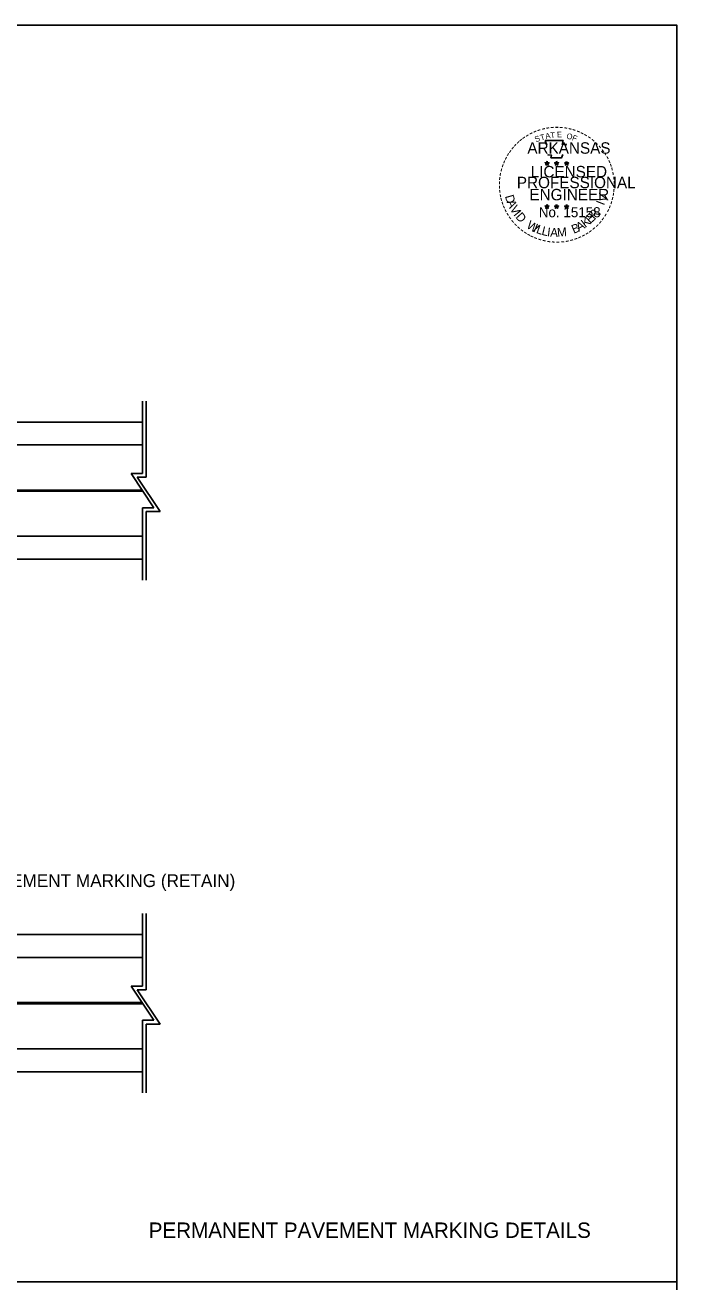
# Model space of a CAD drawing. Extents: x 1372926 to 1373096, y 381240 to 381790.
# Drawn here: x 1373038.9 to 1373096, y 381680.2 to 381790.2 of the extents above; entities that cross this region are included whole.
import ezdxf

# ---------------------------------------------------------------- set-up
doc = ezdxf.new("R2010")
doc.units = 0
for name, color, linetype in [('Default', 7, 'Continuous'), ('DSN_DRFT_Junk-No-Plot', 7, 'Continuous'), ('R_Border Notes', 7, 'Continuous'), ('R_Draft', 7, 'Continuous'), ('SHET_Border-Text', 7, 'Continuous')]:
    doc.layers.add(name, color=color, linetype=linetype)

msp = doc.modelspace()

# ---------------------------------------------------------------- linework, layer by layer
at = {"layer": 'Default'}
for p, q in [((1373049.17, 381757.27), (1373049.17, 381750.93)), ((1373049.5, 381757.27), (1373049.5, 381750.6)), ((1373049.17, 381750.93), (1373048.17, 381750.93)), ((1373050.17, 381747.93), (1373048.17, 381750.93)), ((1373050.72, 381747.6), (1373048.72, 381750.6)), ((1373049.5, 381750.6), (1373048.72, 381750.6)), ((1373049.17, 381741.59), (1373049.17, 381747.93)), ((1373049.17, 381747.93), (1373050.17, 381747.93)), ((1373049.5, 381741.59), (1373049.5, 381747.6)), ((1373049.5, 381747.6), (1373050.72, 381747.6)), ((1373049.17, 381712.41), (1373049.17, 381706.07)), ((1373049.5, 381712.41), (1373049.5, 381705.74)), ((1373049.17, 381706.07), (1373048.17, 381706.07)), ((1373050.17, 381703.07), (1373048.17, 381706.07)), ((1373050.72, 381702.74), (1373048.72, 381705.74)), ((1373049.5, 381705.74), (1373048.72, 381705.74)), ((1373049.17, 381696.73), (1373049.17, 381703.07)), ((1373049.17, 381703.07), (1373050.17, 381703.07)), ((1373049.5, 381696.73), (1373049.5, 381702.74)), ((1373049.5, 381702.74), (1373050.72, 381702.74))]:
    msp.add_line(p, q, dxfattribs=at)
for points in [[(1372925.97, 381790.17), (1372925.97, 381680.17), (1373095.97, 381680.17), (1373095.97, 381790.17)], [(1372925.97, 381680.17), (1372925.97, 381570.17), (1373095.97, 381570.17), (1373095.97, 381680.17)]]:
    msp.add_lwpolyline(points, close=True, dxfattribs=at)
at = {"layer": 'DSN_DRFT_Junk-No-Plot'}
for points in [[(1372925.97, 381790.17), (1373095.97, 381790.17), (1373095.97, 381680.17), (1372925.97, 381680.17)], [(1372925.97, 381790.17), (1372925.97, 381680.17), (1373095.97, 381680.17), (1373095.97, 381790.17)], [(1372925.97, 381680.17), (1373095.97, 381680.17), (1373095.97, 381570.17), (1372925.97, 381570.17)], [(1372925.97, 381680.17), (1372925.97, 381570.17), (1373095.97, 381570.17), (1373095.97, 381680.17)]]:
    msp.add_lwpolyline(points, close=True, dxfattribs=at)
at = {"layer": 'R_Draft'}
for p, q in [((1372972.78, 381755.43), (1373049.17, 381755.43)), ((1372972.78, 381753.43), (1373049.17, 381753.43)), ((1372972.74, 381749.48), (1373049.14, 381749.48)), ((1372972.81, 381749.38), (1373049.2, 381749.38)), ((1372972.78, 381745.43), (1373049.17, 381745.43)), ((1372972.78, 381743.43), (1373049.17, 381743.43)), ((1372972.78, 381710.57), (1373049.17, 381710.57)), ((1372972.78, 381708.57), (1373049.17, 381708.57)), ((1372972.74, 381704.62), (1373049.14, 381704.62)), ((1372972.81, 381704.52), (1373049.2, 381704.52)), ((1372972.78, 381700.57), (1373049.17, 381700.57)), ((1372972.78, 381698.57), (1373049.17, 381698.57))]:
    msp.add_line(p, q, dxfattribs=at)
at = {"layer": 'SHET_Border-Text'}
for p, q in [((1373084.43, 381778.13), (1373084.6, 381778.07)), ((1373084.43, 381778.13), (1373084.56, 381778.11)), ((1373084.43, 381778.13), (1373084.55, 381778.07)), ((1373084.6, 381778.26), (1373084.58, 381778.13)), ((1373084.6, 381778.07), (1373084.6, 381778.26)), ((1373084.6, 381778.26), (1373084.63, 381778.13)), ((1373084.78, 381778.13), (1373084.6, 381778.07)), ((1373084.78, 381778.13), (1373084.63, 381778.11)), ((1373084.78, 381778.13), (1373084.67, 381778.08)), ((1373085.26, 381778.13), (1373085.44, 381778.07)), ((1373085.26, 381778.13), (1373085.39, 381778.11)), ((1373085.26, 381778.13), (1373085.38, 381778.07)), ((1373085.44, 381778.26), (1373085.42, 381778.13)), ((1373085.44, 381778.07), (1373085.44, 381778.26)), ((1373085.44, 381778.26), (1373085.46, 381778.13)), ((1373085.61, 381778.13), (1373085.44, 381778.07)), ((1373085.61, 381778.13), (1373085.47, 381778.11)), ((1373085.61, 381778.13), (1373085.51, 381778.08)), ((1373086.15, 381778.12), (1373086.32, 381778.07)), ((1373086.15, 381778.12), (1373086.27, 381778.1)), ((1373086.15, 381778.12), (1373086.26, 381778.06)), ((1373086.32, 381778.25), (1373086.3, 381778.12)), ((1373086.32, 381778.07), (1373086.32, 381778.25)), ((1373086.32, 381778.25), (1373086.34, 381778.13)), ((1373086.49, 381778.12), (1373086.32, 381778.07)), ((1373086.49, 381778.12), (1373086.35, 381778.1)), ((1373086.49, 381778.12), (1373086.39, 381778.07)), ((1373084.5, 381777.93), (1373084.6, 381778.07)), ((1373084.5, 381777.93), (1373084.56, 381778.05)), ((1373084.5, 381777.93), (1373084.6, 381778.03)), ((1373084.71, 381777.93), (1373084.6, 381778.07)), ((1373084.71, 381777.93), (1373084.6, 381778.03)), ((1373084.71, 381777.93), (1373084.64, 381778.07)), ((1373085.33, 381777.93), (1373085.44, 381778.07)), ((1373085.33, 381777.93), (1373085.39, 381778.05)), ((1373085.33, 381777.93), (1373085.44, 381778.03)), ((1373085.54, 381777.93), (1373085.44, 381778.07)), ((1373085.54, 381777.93), (1373085.44, 381778.03)), ((1373085.54, 381777.93), (1373085.48, 381778.07)), ((1373086.21, 381777.92), (1373086.32, 381778.07)), ((1373086.21, 381777.92), (1373086.28, 381778.04)), ((1373086.21, 381777.92), (1373086.32, 381778.03)), ((1373086.43, 381777.92), (1373086.32, 381778.07)), ((1373086.43, 381777.92), (1373086.32, 381778.03)), ((1373086.43, 381777.92), (1373086.36, 381778.07)), ((1373084.43, 381774.34), (1373084.6, 381774.29)), ((1373084.43, 381774.34), (1373084.55, 381774.32)), ((1373084.43, 381774.34), (1373084.55, 381774.28)), ((1373084.49, 381774.14), (1373084.6, 381774.29)), ((1373084.49, 381774.14), (1373084.56, 381774.26)), ((1373084.49, 381774.14), (1373084.6, 381774.25)), ((1373084.6, 381774.47), (1373084.58, 381774.34)), ((1373084.6, 381774.29), (1373084.6, 381774.47)), ((1373084.6, 381774.47), (1373084.63, 381774.35)), ((1373084.77, 381774.34), (1373084.6, 381774.29)), ((1373084.71, 381774.14), (1373084.6, 381774.29)), ((1373084.71, 381774.14), (1373084.6, 381774.25)), ((1373084.77, 381774.34), (1373084.63, 381774.32)), ((1373084.71, 381774.14), (1373084.64, 381774.28)), ((1373084.77, 381774.34), (1373084.67, 381774.29)), ((1373085.26, 381774.34), (1373085.44, 381774.29)), ((1373085.26, 381774.34), (1373085.39, 381774.32)), ((1373085.26, 381774.34), (1373085.38, 381774.28)), ((1373085.33, 381774.14), (1373085.44, 381774.29)), ((1373085.33, 381774.14), (1373085.39, 381774.26)), ((1373085.33, 381774.14), (1373085.43, 381774.25)), ((1373085.44, 381774.47), (1373085.42, 381774.34)), ((1373085.54, 381774.14), (1373085.43, 381774.25)), ((1373085.44, 381774.29), (1373085.44, 381774.47)), ((1373085.44, 381774.47), (1373085.46, 381774.35)), ((1373085.61, 381774.34), (1373085.44, 381774.29)), ((1373085.54, 381774.14), (1373085.44, 381774.29)), ((1373085.61, 381774.34), (1373085.47, 381774.32)), ((1373085.54, 381774.14), (1373085.47, 381774.28)), ((1373085.61, 381774.34), (1373085.51, 381774.29)), ((1373086.14, 381774.34), (1373086.32, 381774.28)), ((1373086.14, 381774.34), (1373086.27, 381774.32)), ((1373086.14, 381774.34), (1373086.26, 381774.28)), ((1373086.21, 381774.13), (1373086.32, 381774.28)), ((1373086.21, 381774.13), (1373086.27, 381774.26)), ((1373086.21, 381774.13), (1373086.32, 381774.24)), ((1373086.32, 381774.47), (1373086.3, 381774.34)), ((1373086.32, 381774.28), (1373086.32, 381774.47)), ((1373086.32, 381774.47), (1373086.34, 381774.34)), ((1373086.49, 381774.34), (1373086.32, 381774.28)), ((1373086.43, 381774.13), (1373086.32, 381774.28)), ((1373086.43, 381774.13), (1373086.32, 381774.24)), ((1373086.49, 381774.34), (1373086.35, 381774.31)), ((1373086.43, 381774.13), (1373086.36, 381774.28)), ((1373086.49, 381774.34), (1373086.39, 381774.29))]:
    msp.add_line(p, q, dxfattribs=at)
for points in [[(1373084.45, 381780.07), (1373084.58, 381779.66)], [(1373086.2, 381779.61), (1373086.28, 381779.75), (1373085.93, 381779.74), (1373086.01, 381780.07), (1373084.45, 381780.07)], [(1373084.6, 381778.26), (1373084.71, 381777.93), (1373084.43, 381778.13), (1373084.78, 381778.13), (1373084.5, 381777.93), (1373084.6, 381778.26)], [(1373084.7, 381778.86), (1373084.7, 381778.81), (1373084.98, 381778.8), (1373084.95, 381778.57), (1373085.88, 381778.57), (1373085.99, 381778.84)], [(1373085.44, 381778.26), (1373085.54, 381777.93), (1373085.26, 381778.13), (1373085.61, 381778.13), (1373085.33, 381777.93), (1373085.44, 381778.26)], [(1373086.32, 381778.25), (1373086.43, 381777.92), (1373086.15, 381778.12), (1373086.49, 381778.12), (1373086.21, 381777.92), (1373086.32, 381778.25)], [(1373084.6, 381774.47), (1373084.71, 381774.14), (1373084.43, 381774.34), (1373084.77, 381774.34), (1373084.49, 381774.14), (1373084.6, 381774.47)], [(1373085.44, 381774.47), (1373085.54, 381774.14), (1373085.26, 381774.34), (1373085.61, 381774.34), (1373085.33, 381774.14), (1373085.44, 381774.47)], [(1373086.32, 381774.47), (1373086.43, 381774.13), (1373086.14, 381774.34), (1373086.49, 381774.34), (1373086.21, 381774.13), (1373086.32, 381774.47)]]:
    msp.add_lwpolyline(points, dxfattribs=at)
for centre, radius in [((1373084.6, 381778.07), 0.0861), ((1373084.6, 381778.07), 0.0723), ((1373084.6, 381778.07), 0.0579), ((1373084.6, 381778.07), 0.0495), ((1373084.6, 381778.07), 0.0374), ((1373085.44, 381778.07), 0.0861), ((1373085.44, 381778.07), 0.0723), ((1373085.44, 381778.07), 0.0579), ((1373085.44, 381778.07), 0.0495), ((1373085.44, 381778.07), 0.0374), ((1373086.32, 381778.07), 0.0861), ((1373086.32, 381778.07), 0.0723), ((1373086.32, 381778.07), 0.0579), ((1373086.32, 381778.07), 0.0495), ((1373086.32, 381778.07), 0.0374), ((1373084.6, 381778.07), 0.0248), ((1373084.6, 381778.07), 0.0148), ((1373085.44, 381778.07), 0.0248), ((1373085.44, 381778.07), 0.0148), ((1373086.32, 381778.07), 0.0248), ((1373086.32, 381778.07), 0.0148), ((1373084.6, 381774.29), 0.0861), ((1373084.6, 381774.29), 0.0723), ((1373084.6, 381774.29), 0.0579), ((1373084.6, 381774.29), 0.0495), ((1373084.6, 381774.29), 0.0374), ((1373084.6, 381774.29), 0.0248), ((1373084.6, 381774.29), 0.0148), ((1373085.44, 381774.29), 0.0861), ((1373085.44, 381774.29), 0.0723), ((1373085.44, 381774.29), 0.0579), ((1373085.44, 381774.29), 0.0495), ((1373085.44, 381774.29), 0.0374), ((1373085.44, 381774.29), 0.0248), ((1373085.44, 381774.29), 0.0148), ((1373086.32, 381774.28), 0.0861), ((1373086.32, 381774.28), 0.0723), ((1373086.32, 381774.28), 0.0579), ((1373086.32, 381774.28), 0.0495), ((1373086.32, 381774.28), 0.0374), ((1373086.32, 381774.28), 0.0248), ((1373086.32, 381774.28), 0.0148)]:
    msp.add_circle(centre, radius, dxfattribs=at)

# ---------------------------------------------------------------- texts
at = {"layer": 'Default'}
msp.add_text('EXIST. DOUBLE YELLOW THERMOPLASTIC PAVEMENT MARKING (RETAIN)', height=1.125, dxfattribs=at).set_placement((1373002.97, 381714.73))
at = {"layer": 'R_Border Notes'}
msp.add_text('PERMANENT PAVEMENT MARKING DETAILS', height=1.35, dxfattribs=at).set_placement((1373049.72, 381684.02))
at = {"layer": 'SHET_Border-Text'}
for s, height, rotation, p in [('-', 0.8, 36.2317, (1373082.6, 381779.96)), ('-', 0.8, 34.0636, (1373082.89, 381780.15)), ('-', 0.8, 28.7918, (1373083.19, 381780.34)), ('-', 0.8, 24.3072, (1373083.51, 381780.5)), ('S', 0.5, 21.594, (1373083.63, 381779.91)), ('-', 0.8, 19.1761, (1373083.82, 381780.63)), ('T', 0.5, 16.4036, (1373084.08, 381780.07)), ('-', 0.8, 13.6302, (1373084.2, 381780.75)), ('A', 0.5, 11.2132, (1373084.5, 381780.2)), ('-', 0.8, 10.2193, (1373084.54, 381780.83)), ('T', 0.5, 6.0228, (1373084.92, 381780.28)), ('-', 0.8, 5.8968, (1373084.9, 381780.89)), ('-', 0.8, 0.1862, (1373085.29, 381780.92)), ('E', 0.5, 0.8323, (1373085.47, 381780.34)), ('-', 0.8, 357.743, (1373085.65, 381780.92)), ('-', 0.8, 352.1617, (1373086.02, 381780.89)), ('O', 0.5, 350.4515, (1373086.28, 381780.23)), ('-', 0.8, 347.2049, (1373086.38, 381780.83)), ('F', 0.5, 340.0707, (1373086.75, 381780.12)), ('-', 0.8, 342.3362, (1373086.7, 381780.76)), ('-', 0.8, 337.8551, (1373087.07, 381780.64)), ('-', 0.8, 334.1211, (1373087.38, 381780.51)), ('-', 0.8, 329.6409, (1373087.67, 381780.37)), ('-', 0.8, 325.8627, (1373087.99, 381780.19)), ('-', 0.8, 54.2325, (1373081.52, 381778.79)), ('-', 0.8, 50.6142, (1373081.72, 381779.08)), ('-', 0.8, 48.4231, (1373081.92, 381779.32)), ('-', 0.8, 42.9622, (1373082.15, 381779.56)), ('-', 0.8, 38.9507, (1373082.36, 381779.77)), ('-', 0.8, 320.5297, (1373088.3, 381779.97)), ('-', 0.8, 315.5786, (1373088.6, 381779.73)), ('-', 0.8, 309.8797, (1373088.88, 381779.45)), ('-', 0.8, 306.6522, (1373089.14, 381779.15)), ('-', 0.8, 67.7743, (1373081.07, 381777.92)), ('-', 0.8, 62.8713, (1373081.2, 381778.22)), ('-', 0.8, 58.0706, (1373081.35, 381778.53)), ('-', 0.7, 303.6753, (1373089.39, 381778.87)), ('-', 0.8, 299.6684, (1373089.55, 381778.57)), ('-', 0.8, 294.6628, (1373089.71, 381778.26)), ('-', 0.8, 81.2013, (1373080.79, 381776.89)), ('-', 0.8, 75.461, (1373080.86, 381777.25)), ('-', 0.8, 72.3945, (1373080.96, 381777.6)), ('-', 0.8, 290.5728, (1373089.84, 381777.97)), ('-', 0.8, 285.1233, (1373089.95, 381777.68)), ('-', 0.8, 280.5493, (1373090.05, 381777.31)), ('-', 0.8, 94.1959, (1373080.76, 381775.83)), ('-', 0.8, 89.0622, (1373080.74, 381776.19)), ('-', 0.8, 85.1863, (1373080.75, 381776.54)), ('-', 0.8, 276.5962, (1373090.13, 381776.93)), ('-', 0.8, 274.3301, (1373090.16, 381776.57)), ('-', 0.8, 269.9407, (1373090.18, 381776.25)), ('-', 0.8, 98.9479, (1373080.8, 381775.5)), ('-', 0.8, 101.7149, (1373080.86, 381775.13)), ('-', 0.8, 105.4578, (1373080.94, 381774.83)), ('D', 0.77, 286.2848, (1373080.91, 381775.2)), ('I', 0.77, 69.0301, (1373089.59, 381774.35)), ('V', 0.77, 72.6573, (1373089.7, 381774.62)), ('-', 0.8, 255.7626, (1373090.08, 381775.25)), ('-', 0.8, 260.9953, (1373090.14, 381775.59)), ('-', 0.8, 263.5172, (1373090.17, 381775.92)), ('-', 0.8, 109.0874, (1373081.05, 381774.52)), ('-', 0.8, 114.0643, (1373081.18, 381774.22)), ('-', 0.8, 115.7289, (1373081.33, 381773.91)), ('-', 0.8, 120.4471, (1373081.51, 381773.62)), ('A', 0.77, 292.7835, (1373081.05, 381774.7)), ('V', 0.77, 300.7936, (1373081.31, 381774.11)), ('I', 0.77, 308.3502, (1373081.63, 381773.59)), ('D', 0.77, 311.9774, (1373081.8, 381773.36)), ('E', 0.77, 44.0175, (1373088.4, 381772.75)), ('R', 0.77, 50.3651, (1373088.77, 381773.11)), (',', 0.77, 57.4684, (1373089.13, 381773.55)), ('-', 0.8, 244.6197, (1373089.75, 381774.24)), ('-', 0.8, 247.8887, (1373089.88, 381774.55)), ('-', 0.8, 252.8681, (1373089.99, 381774.89)), ('-', 0.8, 125.8934, (1373081.71, 381773.34)), ('-', 0.8, 130.7181, (1373081.94, 381773.06)), ('-', 0.8, 134.2238, (1373082.2, 381772.79)), ('W', 0.77, 328.0731, (1373082.74, 381772.47)), ('I', 0.77, 336.6877, (1373083.33, 381772.12)), ('L', 0.77, 340.3149, (1373083.6, 381772)), ('B', 0.77, 22.8589, (1373086.94, 381771.9)), ('A', 0.77, 28.9042, (1373087.39, 381772.09)), ('K', 0.77, 36.9143, (1373087.95, 381772.41)), ('-', 0.8, 225.7653, (1373088.9, 381772.97)), ('-', 0.8, 231.2538, (1373089.14, 381773.25)), ('-', 0.8, 233.8452, (1373089.35, 381773.54)), ('-', 0.8, 239.0712, (1373089.55, 381773.86)), ('-', 0.8, 138.9338, (1373082.46, 381772.56)), ('-', 0.8, 144.6463, (1373082.74, 381772.35)), ('-', 0.8, 148.0898, (1373083.02, 381772.17)), ('-', 0.8, 151.5704, (1373083.31, 381772.01)), ('-', 0.8, 154.6002, (1373083.57, 381771.88)), ('-', 0.8, 158.5612, (1373083.88, 381771.76)), ('L', 0.77, 346.6625, (1373084.08, 381771.83)), ('I', 0.77, 353.0101, (1373084.58, 381771.71)), ('A', 0.77, 356.6373, (1373084.86, 381771.66)), ('M', 0.77, 4.6473, (1373085.51, 381771.64)), ('-', 0.8, 199.4643, (1373087.19, 381771.82)), ('-', 0.8, 204.2516, (1373087.5, 381771.96)), ('-', 0.8, 207.3568, (1373087.81, 381772.12)), ('-', 0.8, 212.2491, (1373088.09, 381772.29)), ('-', 0.8, 215.7363, (1373088.36, 381772.48)), ('-', 0.8, 221.0851, (1373088.63, 381772.72)), ('-', 0.8, 162.7983, (1373084.23, 381771.65)), ('-', 0.8, 167.5555, (1373084.59, 381771.57)), ('-', 0.8, 173.1155, (1373084.97, 381771.51)), ('-', 0.8, 176.5183, (1373085.35, 381771.49)), ('-', 0.8, 181.5918, (1373085.72, 381771.49)), ('-', 0.8, 185.8167, (1373086.12, 381771.53)), ('-', 0.8, 191.2858, (1373086.49, 381771.6)), ('-', 0.8, 195.4743, (1373086.85, 381771.7))]:
    msp.add_text(s, height=height, rotation=rotation, dxfattribs=at).set_placement(p)
for s, height, p in [('ARKANSAS', 1, (1373082.88, 381778.92)), ('LICENSED', 1, (1373083.17, 381776.85)), ('PROFESSIONAL', 1, (1373081.96, 381775.9)), ('ENGINEER', 1, (1373083.06, 381774.84)), ('No. 15158', 0.878, (1373083.88, 381773.36)), ('AAMU', 0.00001, (1373085.4, 381771.63))]:
    msp.add_text(s, height=height, dxfattribs=at).set_placement(p)

doc.saveas('drawing.dxf')
